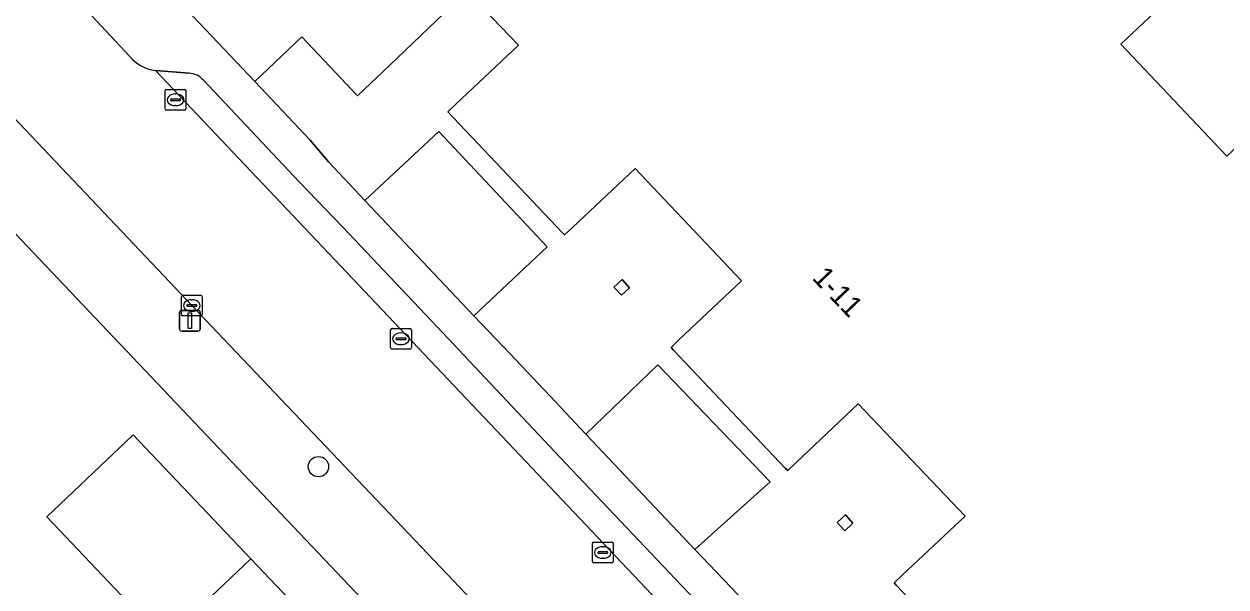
# Model space of a CAD drawing. Extents: x 162523 to 163266, y 381230 to 382050.
# Drawn here: x 163097.3 to 163155, y 381485 to 381512.1 of the extents above; entities that cross this region are included whole.
import ezdxf

# ---------------------------------------------------------------- set-up
doc = ezdxf.new("R2010")
doc.units = 0
for name, color, linetype in [('IMGEO_Boom', 7, 'Continuous'), ('IMGEO_Erf', 7, 'Continuous'), ('IMGEO_Groenvoorziening', 7, 'Continuous'), ('IMGEO_Haag', 7, 'Continuous'), ('IMGEO_Kolk', 7, 'Continuous'), ('IMGEO_Lichtmast', 7, 'Continuous'), ('IMGEO_Muur', 7, 'Continuous'), ('IMGEO_Pand', 7, 'Continuous'), ('IMGEO_Pand_nummerreeks', 7, 'Continuous'), ('IMGEO_Parkeervlak_open', 7, 'Continuous'), ('IMGEO_Rijbaan_lokaal_open', 7, 'Continuous'), ('IMGEO_Voetpad_open', 7, 'Continuous')]:
    doc.layers.add(name, color=color, linetype=linetype)

msp = doc.modelspace()

# ---------------------------------------------------------------- linework, layer by layer
at = {"layer": 'IMGEO_Boom'}
msp.add_circle((163111.405, 381490.823), 0.489, dxfattribs=at)
at = {"layer": 'IMGEO_Erf'}
for points in [[(163165.684, 381515.776), (163163.611, 381517.256), (163161.317, 381518.895), (163159.263, 381520.362), (163153.204, 381514.52), (163153.359, 381514.353), (163152.966, 381513.984), (163149.97, 381511.156), (163155.068, 381505.759), (163158.072, 381508.581), (163158.462, 381508.95), (163158.651, 381508.767)], [(163125.606, 381499.46), (163126, 381499.823), (163126.363, 381499.429), (163125.973, 381499.069)], [(163136.346, 381488.138), (163136.737, 381488.5), (163137.1, 381488.107), (163136.71, 381487.742)]]:
    msp.add_lwpolyline(points, close=True, dxfattribs=at)
for points in [[(163164.14, 381431.046), (163132.502, 381464.414), (163084.908, 381514.61)], [(163144.553, 381479.441), (163139.198, 381485.108), (163139.079, 381485.231), (163139.463, 381485.6), (163142.491, 381488.433), (163137.348, 381493.841), (163134.358, 381491.008), (163133.966, 381490.637), (163133.849, 381490.758), (163128.474, 381496.43), (163128.359, 381496.552), (163128.733, 381496.93), (163131.741, 381499.757), (163126.624, 381505.172), (163123.626, 381502.334), (163123.24, 381501.968), (163123.134, 381502.08), (163117.902, 381507.607), (163117.634, 381507.89), (163118.007, 381508.267), (163121.025, 381511.101), (163118.543, 381513.705), (163115.579, 381510.842), (163115.194, 381510.473), (163113.282, 381508.663), (163110.605, 381511.507), (163108.343, 381509.358), (163111.016, 381506.526), (163111.89, 381505.496), (163113.645, 381503.623), (163117.199, 381506.949), (163122.4, 381501.391), (163118.88, 381498.086), (163120.61, 381496.261), (163122.544, 381494.214), (163124.263, 381492.39), (163127.729, 381495.715), (163133.118, 381490.099), (163129.505, 381486.843), (163131.231, 381485.018)], [(163114.481, 381447.632), (163118.435, 381451.383), (163112.57, 381457.562), (163115.448, 381460.293), (163099.031, 381477.589), (163098.961, 381477.663), (163104.001, 381482.447), (163098.348, 381488.402), (163102.509, 381492.351), (163108.162, 381486.396), (163130.674, 381462.68), (163126.725, 381458.93), (163136.166, 381448.983)]]:
    msp.add_lwpolyline(points, dxfattribs=at)
at = {"layer": 'IMGEO_Groenvoorziening'}
for points in [[(163117.199, 381506.949), (163113.645, 381503.623), (163118.88, 381498.086), (163122.4, 381501.391)], [(163127.729, 381495.715), (163124.263, 381492.39), (163129.505, 381486.843), (163133.118, 381490.099)]]:
    msp.add_lwpolyline(points, close=True, dxfattribs=at)
at = {"layer": 'IMGEO_Haag'}
for points in [[(163117.199, 381506.949), (163113.645, 381503.623), (163118.88, 381498.086), (163122.4, 381501.391)], [(163127.729, 381495.715), (163124.263, 381492.39), (163129.505, 381486.843), (163133.118, 381490.099)]]:
    msp.add_lwpolyline(points, close=True, dxfattribs=at)
at = {"layer": 'IMGEO_Kolk'}
for p, q in [((163104.04, 381508.046), (163104.04, 381508.898)), ((163104.115, 381508.972), (163104.967, 381508.972)), ((163104.528, 381508.752), (163104.553, 381508.752)), ((163105.041, 381508.898), (163105.041, 381508.046)), ((163104.299, 381508.466), (163104.299, 381508.478)), ((163104.737, 381508.429), (163104.339, 381508.429)), ((163104.342, 381508.515), (163104.74, 381508.515)), ((163104.551, 381508.192), (163104.526, 381508.192)), ((163104.783, 381508.478), (163104.783, 381508.466)), ((163104.967, 381507.972), (163104.115, 381507.972)), ((163104.822, 381498.148), (163104.822, 381499)), ((163104.897, 381499.074), (163105.749, 381499.074)), ((163105.823, 381499), (163105.823, 381498.148)), ((163105.081, 381498.568), (163105.081, 381498.58)), ((163105.519, 381498.531), (163105.121, 381498.531)), ((163105.124, 381498.617), (163105.522, 381498.617)), ((163105.31, 381498.854), (163105.335, 381498.854)), ((163105.565, 381498.58), (163105.565, 381498.568)), ((163105.749, 381498.074), (163104.897, 381498.074)), ((163105.333, 381498.294), (163105.308, 381498.294)), ((163114.874, 381496.548), (163114.874, 381497.4)), ((163114.949, 381497.474), (163115.801, 381497.474)), ((163115.362, 381497.254), (163115.387, 381497.254)), ((163115.875, 381497.4), (163115.875, 381496.548)), ((163115.133, 381496.968), (163115.133, 381496.98)), ((163115.571, 381496.931), (163115.173, 381496.931)), ((163115.176, 381497.017), (163115.574, 381497.017)), ((163115.385, 381496.694), (163115.36, 381496.694)), ((163115.617, 381496.98), (163115.617, 381496.968)), ((163115.801, 381496.474), (163114.949, 381496.474)), ((163124.575, 381486.267), (163124.575, 381487.119)), ((163124.65, 381487.193), (163125.502, 381487.193)), ((163125.063, 381486.973), (163125.088, 381486.973)), ((163125.576, 381487.119), (163125.576, 381486.267)), ((163125.502, 381486.193), (163124.65, 381486.193)), ((163124.834, 381486.687), (163124.834, 381486.699)), ((163125.272, 381486.65), (163124.874, 381486.65)), ((163124.877, 381486.736), (163125.275, 381486.736)), ((163125.086, 381486.413), (163125.061, 381486.413)), ((163125.318, 381486.699), (163125.318, 381486.687))]:
    msp.add_line(p, q, dxfattribs=at)
for points in [[(163104.04, 381508.046), (163104.04, 381508.898)], [(163104.115, 381508.972), (163104.967, 381508.972)], [(163105.041, 381508.898), (163105.041, 381508.046)], [(163104.967, 381507.972), (163104.115, 381507.972)], [(163104.822, 381498.148), (163104.822, 381499)], [(163104.897, 381499.074), (163105.749, 381499.074)], [(163105.823, 381499), (163105.823, 381498.148)], [(163105.749, 381498.074), (163104.897, 381498.074)], [(163114.874, 381496.548), (163114.874, 381497.4)], [(163114.949, 381497.474), (163115.801, 381497.474)], [(163115.875, 381497.4), (163115.875, 381496.548)], [(163115.801, 381496.474), (163114.949, 381496.474)], [(163124.575, 381486.267), (163124.575, 381487.119)], [(163124.65, 381487.193), (163125.502, 381487.193)], [(163125.576, 381487.119), (163125.576, 381486.267)], [(163125.502, 381486.193), (163124.65, 381486.193)]]:
    msp.add_lwpolyline(points, dxfattribs=at)
for centre, radius, start, end in [((163104.117, 381508.896), 0.0765, 91.55205, 178.44795), ((163104.117, 381508.896), 0.0765, 91.55205, 178.44795), ((163104.965, 381508.896), 0.0765, 1.55205, 88.44795), ((163104.965, 381508.896), 0.0765, 1.55205, 88.44795), ((163104.339, 381508.475), 0.0403, 85.87752, 175.75265), ((163104.336, 381508.465), 0.0366, 178.93798, 274.71019), ((163104.74, 381508.472), 0.043, 264.86636, 352.45326), ((163104.744, 381508.477), 0.0386, 1.73085, 96.63898), ((163104.117, 381508.048), 0.0765, 181.55205, 268.44795), ((163104.117, 381508.048), 0.0765, 181.55205, 268.44795), ((163104.965, 381508.048), 0.0765, 271.55205, 358.44795), ((163104.965, 381508.048), 0.0765, 271.55205, 358.44795), ((163104.899, 381498.998), 0.0765, 91.55205, 178.44795), ((163104.899, 381498.998), 0.0765, 91.55205, 178.44795), ((163105.747, 381498.998), 0.0765, 1.55205, 88.44795), ((163105.747, 381498.998), 0.0765, 1.55205, 88.44795), ((163105.121, 381498.577), 0.0403, 85.87752, 175.75265), ((163105.118, 381498.567), 0.0366, 178.93798, 274.71019), ((163105.522, 381498.574), 0.043, 264.86636, 352.45326), ((163105.526, 381498.579), 0.0386, 1.73085, 96.63898), ((163104.899, 381498.15), 0.0765, 181.55205, 268.44795), ((163104.899, 381498.15), 0.0765, 181.55205, 268.44795), ((163105.747, 381498.15), 0.0765, 271.55205, 358.44795), ((163105.747, 381498.15), 0.0765, 271.55205, 358.44795), ((163114.951, 381497.398), 0.0765, 91.55205, 178.44795), ((163114.951, 381497.398), 0.0765, 91.55205, 178.44795), ((163115.799, 381497.398), 0.0765, 1.55205, 88.44795), ((163115.799, 381497.398), 0.0765, 1.55205, 88.44795), ((163115.173, 381496.977), 0.0403, 85.87752, 175.75265), ((163115.17, 381496.967), 0.0366, 178.93798, 274.71019), ((163115.574, 381496.974), 0.043, 264.86636, 352.45326), ((163115.578, 381496.979), 0.0386, 1.73085, 96.63898), ((163114.951, 381496.55), 0.0765, 181.55205, 268.44795), ((163114.951, 381496.55), 0.0765, 181.55205, 268.44795), ((163115.799, 381496.55), 0.0765, 271.55205, 358.44795), ((163115.799, 381496.55), 0.0765, 271.55205, 358.44795), ((163124.652, 381487.117), 0.0765, 91.55205, 178.44795), ((163124.652, 381487.117), 0.0765, 91.55205, 178.44795), ((163125.5, 381487.117), 0.0765, 1.55205, 88.44795), ((163125.5, 381487.117), 0.0765, 1.55205, 88.44795), ((163124.652, 381486.269), 0.0765, 181.55205, 268.44795), ((163124.652, 381486.269), 0.0765, 181.55205, 268.44795), ((163124.874, 381486.696), 0.0403, 85.87752, 175.75265), ((163124.871, 381486.686), 0.0366, 178.93798, 274.71019), ((163125.275, 381486.693), 0.043, 264.86636, 352.45326), ((163125.279, 381486.698), 0.0386, 1.73085, 96.63898), ((163125.5, 381486.269), 0.0765, 271.55205, 358.44795), ((163125.5, 381486.269), 0.0765, 271.55205, 358.44795)]:
    msp.add_arc(centre, radius, start, end, dxfattribs=at)
for centre, major_axis, ratio, start_param, end_param in [((163104.527, 381508.472), (-0.387, 0.002), 0.722429, 4.712389, 7.853982), ((163104.552, 381508.472), (-0.39, 0.002), 0.717154, 1.570796, 4.712389), ((163105.309, 381498.574), (-0.387, 0.002), 0.722429, 4.712389, 7.853982), ((163105.334, 381498.574), (-0.39, 0.002), 0.717154, 1.570796, 4.712389), ((163115.361, 381496.974), (-0.387, 0.002), 0.722429, 4.712389, 7.853982), ((163115.386, 381496.974), (-0.39, 0.002), 0.717154, 1.570796, 4.712389), ((163125.062, 381486.693), (-0.387, 0.002), 0.722429, 4.712389, 7.853982), ((163125.087, 381486.693), (-0.39, 0.002), 0.717154, 1.570796, 4.712389)]:
    msp.add_ellipse(centre, major_axis=major_axis, ratio=ratio, start_param=start_param, end_param=end_param, dxfattribs=at)
at = {"layer": 'IMGEO_Lichtmast'}
for p, q in [((163104.833, 381498.342), (163105.623, 381498.342)), ((163105.623, 381498.342), (163104.833, 381498.342)), ((163104.733, 381497.442), (163104.733, 381498.242)), ((163104.733, 381498.242), (163104.733, 381497.442)), ((163105.723, 381498.242), (163105.723, 381497.442)), ((163105.723, 381497.442), (163105.723, 381498.242)), ((163105.623, 381497.342), (163104.833, 381497.342)), ((163104.833, 381497.342), (163105.623, 381497.342))]:
    msp.add_line(p, q, dxfattribs=at)
msp.add_lwpolyline([(163105.153, 381498.217), (163105.303, 381498.217), (163105.303, 381497.467), (163105.153, 381497.467), (163105.153, 381498.217)], dxfattribs=at)
for centre, start, end in [((163104.833, 381498.242), 90, 180), ((163104.833, 381498.242), 90, 180), ((163105.623, 381498.242), 0, 90), ((163105.623, 381498.242), 360, 90), ((163104.833, 381497.442), 180, 270), ((163104.833, 381497.442), 180, 270), ((163105.623, 381497.442), 270, 0), ((163105.623, 381497.442), 270, 0)]:
    msp.add_arc(centre, 0.1, start, end, dxfattribs=at)
at = {"layer": 'IMGEO_Muur'}
msp.add_lwpolyline([(163111.016, 381506.526), (163108.343, 381509.358)], dxfattribs=at)
at = {"layer": 'IMGEO_Pand'}
for points in [[(163102.711, 381515.323), (163108.343, 381509.358), (163110.605, 381511.507), (163113.282, 381508.663), (163115.194, 381510.473), (163115.579, 381510.842), (163118.543, 381513.705), (163121.025, 381511.101), (163118.007, 381508.267), (163117.634, 381507.89), (163117.902, 381507.607), (163123.134, 381502.08), (163123.24, 381501.968), (163123.626, 381502.334), (163126.624, 381505.172), (163131.741, 381499.757), (163128.733, 381496.93), (163128.359, 381496.552), (163128.474, 381496.43), (163133.849, 381490.758), (163133.966, 381490.637), (163134.358, 381491.008), (163137.348, 381493.841), (163142.491, 381488.433), (163139.463, 381485.6), (163139.079, 381485.231), (163139.198, 381485.108), (163144.553, 381479.441)], [(163155.068, 381505.759), (163149.97, 381511.156), (163152.966, 381513.984)]]:
    msp.add_lwpolyline(points, dxfattribs=at)
for points in [[(163125.606, 381499.46), (163125.973, 381499.069), (163126.363, 381499.429), (163126, 381499.823)], [(163098.348, 381488.402), (163104.001, 381482.447), (163108.162, 381486.396), (163102.509, 381492.351)], [(163136.346, 381488.138), (163136.71, 381487.742), (163137.1, 381488.107), (163136.737, 381488.5)], [(163108.162, 381486.396), (163104.001, 381482.447), (163098.961, 381477.663), (163099.031, 381477.589), (163115.448, 381460.293), (163112.57, 381457.562), (163118.435, 381451.383), (163126.725, 381458.93), (163130.674, 381462.68)]]:
    msp.add_lwpolyline(points, close=True, dxfattribs=at)
at = {"layer": 'IMGEO_Parkeervlak_open'}
for points in [[(163105.199, 381509.757), (163103.568, 381509.88)], [(163103.568, 381509.88), (163153.839, 381456.764)], [(163110.49, 381504.514), (163105.878, 381509.418)], [(163112.58, 381502.341), (163110.49, 381504.514)], [(163117.116, 381497.542), (163112.58, 381502.341)], [(163123.28, 381490.987), (163117.116, 381497.542)], [(163128.284, 381485.708), (163123.28, 381490.987)], [(163133.961, 381479.729), (163128.284, 381485.708)]]:
    msp.add_lwpolyline(points, dxfattribs=at)
msp.add_arc((163105.101, 381508.71), 1.051, 42.30684, 84.63058, dxfattribs=at)
at = {"layer": 'IMGEO_Rijbaan_lokaal_open'}
for points in [[(163102.323, 381510.571), (163100.274, 381512.762), (163094.355, 381518.519), (163091.451, 381521.34), (163089.836, 381522.91), (163080.697, 381532.76)], [(163076.974, 381528.282), (163079.513, 381525.79), (163086.854, 381518.075), (163086.997, 381517.925), (163089.162, 381515.65), (163103.975, 381500), (163105.324, 381498.575), (163121.57, 381481.459), (163135.737, 381466.525), (163136.881, 381465.319), (163146.524, 381455.102), (163147.369, 381454.206), (163150.172, 381451.237), (163155.025, 381446.086), (163166.031, 381434.407), (163170.413, 381429.933)], [(163153.839, 381456.764), (163103.568, 381509.88)]]:
    msp.add_lwpolyline(points, dxfattribs=at)
msp.add_arc((163103.821, 381511.803), 1.94, 219.43328, 262.50441, dxfattribs=at)
at = {"layer": 'IMGEO_Voetpad_open'}
for points in [[(163080.697, 381532.76), (163089.836, 381522.91), (163091.451, 381521.34), (163094.355, 381518.519), (163100.274, 381512.762), (163102.323, 381510.571)], [(163068.737, 381527.889), (163069.406, 381527.653), (163072.516, 381527.583), (163076.869, 381523.043), (163077.167, 381519.718), (163077.476, 381519.136), (163078.537, 381520.449), (163081.613, 381517.216), (163083.008, 381514.758), (163084.908, 381514.61), (163132.502, 381464.414), (163164.14, 381431.046)], [(163155.025, 381446.086), (163154.664, 381445.741), (163146.963, 381453.818), (163147.369, 381454.206), (163146.524, 381455.102), (163146.16, 381454.755), (163135.32, 381466.126), (163135.737, 381466.525), (163121.57, 381481.459), (163105.324, 381498.575), (163103.975, 381500), (163089.162, 381515.65), (163086.997, 381517.925), (163086.854, 381518.075), (163086.512, 381517.747), (163081.429, 381523.05), (163079.143, 381525.436), (163079.513, 381525.79), (163076.974, 381528.282)], [(163134.903, 381481.158), (163133.175, 381482.974), (163131.231, 381485.018), (163129.505, 381486.843), (163124.263, 381492.39), (163122.544, 381494.214), (163120.61, 381496.261), (163118.88, 381498.086), (163113.645, 381503.623), (163111.89, 381505.496), (163111.016, 381506.526), (163108.343, 381509.358), (163102.711, 381515.323)], [(163103.568, 381509.88), (163105.199, 381509.757)], [(163105.878, 381509.418), (163110.49, 381504.514), (163112.58, 381502.341), (163117.116, 381497.542), (163123.28, 381490.987), (163128.284, 381485.708), (163133.961, 381479.729), (163138.664, 381474.76), (163141.227, 381472.04), (163145.704, 381467.321), (163149.855, 381462.952), (163153.441, 381459.174)]]:
    msp.add_lwpolyline(points, dxfattribs=at)
for centre, radius, start, end in [((163103.821, 381511.803), 1.94, 219.43328, 262.50441), ((163105.101, 381508.71), 1.051, 42.30684, 84.63058)]:
    msp.add_arc(centre, radius, start, end, dxfattribs=at)

# ---------------------------------------------------------------- texts
at = {"layer": 'IMGEO_Pand_nummerreeks'}
msp.add_text('1-11', height=1, rotation=313.63142, dxfattribs=at).set_placement((163135.094, 381499.869))

doc.saveas('drawing.dxf')
